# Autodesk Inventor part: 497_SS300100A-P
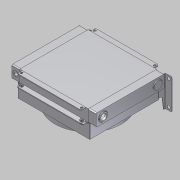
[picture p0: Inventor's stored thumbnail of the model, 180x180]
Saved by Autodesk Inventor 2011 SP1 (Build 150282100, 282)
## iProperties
Created: 2016-01
Document SubType Name: Modeling
Designer: romansazanov
Density: 1 g/cm^3
Mass: 8921.94 g
Surface Area: 11806.7 cm^2
Volume: 8921.94 cm^3
Стандарт преобразования: STEP AP203
Имя файла: SS300100A-P.stp
Препроцессор: THINKDESIGN
Постпроцессор: Build: 282, Release: 2011 SP1 - Date: Thu 08/05/2010
Отправленные единицы: миллиметр
Неопределенность: 0.001
Author: romansazanov
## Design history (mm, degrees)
feature "БазТело1"
feature "БазТело2"
feature "БазТело3"
feature "БазТело4"
feature "БазТело5"
feature "БазТело6"
feature "БазТело7"
feature "БазТело8"
feature "БазТело9"
feature "БазТело10"
feature "БазТело11"
feature "БазТело12"
feature "БазТело13"
feature "БазТело14"
feature "БазТело15"
feature "БазТело16"
feature "БазТело17"
feature "БазТело18"
feature "БазТело19"
feature "БазТело20"
feature "БазТело21"
feature "БазТело22"
feature "БазТело23"
feature "БазТело24"
feature "БазТело25"
feature "БазТело26"
feature "БазТело27"
feature "БазТело28"
feature "БазТело29"
feature "БазТело30"
feature "БазТело31"
feature "БазТело32"
feature "БазТело33"
feature "БазТело34"
feature "БазТело35"
feature "БазТело36"
feature "БазТело37"
feature "БазТело38"
feature "БазТело39"
feature "БазТело40"
feature "БазТело41"
feature "БазТело42"
feature "БазТело43"
feature "БазТело44"
feature "БазТело45"
feature "БазТело46"
feature "БазТело47"
feature "БазТело48"
feature "БазТело49"
feature "БазТело50"
feature "БазТело51"
feature "БазТело52"
feature "БазТело53"
feature "БазТело54"
feature "БазТело55"
feature "БазТело56"
feature "БазТело57"
feature "БазТело58"
feature "БазТело59"
feature "БазТело60"
feature "БазТело61"
feature "БазТело62"
feature "БазТело63"
feature "БазТело64"
feature "БазТело65"
node "None"
node "None_1"
node "None_2"
node "None_3"
node "None_4"
node "None_5"
node "None_6"
node "None_7"
node "None_8"
node "None_9"
node "None_10"
node "None_11"
node "None_12"
node "None_13"
node "None_14"
node "None_15"
node "None_16"
node "None_17"
node "None_18"
node "None_19"
node "None_20"
node "None_21"
node "None_22"
node "None_23"
node "None_24"
node "None_25"
node "None_26"
node "None_27"
node "None_28"
node "None_29"
node "None_30"
node "None_31"
node "None_32"
node "None_33"
node "None_34"
node "None_35"
node "None_36"
node "None_37"
node "None_38"
node "None_39"
node "None_40"
node "None_41"
node "None_42"
node "None_43"
node "None_44"
node "None_45"
node "None_46"
node "None_47"
node "None_48"
node "None_49"
node "None_50"
node "None_51"
node "None_52"
node "None_53"
node "None_54"
node "None_55"
node "None_56"
node "None_57"
node "None_58"
node "None_59"
node "None_60"
node "None_61"
node "None_62"
node "None_63"
node "None_64"
